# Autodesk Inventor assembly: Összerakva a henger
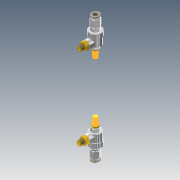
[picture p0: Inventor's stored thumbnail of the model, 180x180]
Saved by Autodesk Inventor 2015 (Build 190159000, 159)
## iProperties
Created: 2012-12
Part Number: Összerakva a henger
Document SubType Name: Assembly
Designer: Marci
Author: Marci
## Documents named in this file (5)
- C:\Users\Andrew Almeida\Documents\Projeto WS2015\WS2015 CAD Data ANLAS\01\Pneumatic System\Engine\Pneumatikus hajtás\Összerakva a henger.iam
- C:\Users\Andrew Almeida\Documents\Projeto WS2015\WS2015 CAD Data ANLAS\01\Pneumatic System\Engine\Pneumatikus hajtás\Hollanderes közcsavar.ipt
- C:\Users\Andrew Almeida\Documents\Projeto WS2015\WS2015 CAD Data ANLAS\01\Pneumatic System\Engine\Pneumatikus hajtás\Gyorsleeresztő szelep.ipt
- C:\Users\Andrew Almeida\Documents\Projeto WS2015\WS2015 CAD Data ANLAS\01\Pneumatic System\Engine\Pneumatikus hajtás\Hangtompító.ipt
- C:\Users\Andrew Almeida\Documents\Projeto WS2015\WS2015 CAD Data ANLAS\01\Pneumatic System\Engine\Pneumatikus hajtás\1.4 12 gyorscsat.ipt
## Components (8 placed, 4 different names)
1. Hollanderes közcsavar:1 — Mate:13, Mate:14
2. Hollanderes közcsavar:2 — Mate:11, Mate:12
3. Gyorsleeresztő szelep:1 — Mate:11, Mate:12, Flush:1, Mate:16, Mate:17, Mate:20, Mate:21
4. Gyorsleeresztő szelep:2 — Mate:13, Mate:14, Flush:2, Mate:18, Mate:19, Mate:22, Mate:23
5. Hangtompító:1 — Mate:16, Mate:17
6. Hangtompító:2 — Mate:18, Mate:19
7. 1.4 12 gyorscsat:1 — Mate:20, Mate:21
8. 1.4 12 gyorscsat:2 — Mate:22, Mate:23
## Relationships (14: Mate 12, Flush 2)
- Mate:11: Hollanderes közcsavar:2 ↔ Gyorsleeresztő szelep:1
- Mate:12: Hollanderes közcsavar:2 ↔ Gyorsleeresztő szelep:1
- Mate:13: Hollanderes közcsavar:1 ↔ Gyorsleeresztő szelep:2
- Mate:14: Hollanderes közcsavar:1 ↔ Gyorsleeresztő szelep:2
- Flush:1: Gyorsleeresztő szelep:1
- Flush:2: Gyorsleeresztő szelep:2
- Mate:16: Gyorsleeresztő szelep:1 ↔ Hangtompító:1
- Mate:17: Gyorsleeresztő szelep:1 ↔ Hangtompító:1
- Mate:18: Gyorsleeresztő szelep:2 ↔ Hangtompító:2
- Mate:19: Gyorsleeresztő szelep:2 ↔ Hangtompító:2
- Mate:20: Gyorsleeresztő szelep:1 ↔ 1.4 12 gyorscsat:1
- Mate:21: Gyorsleeresztő szelep:1 ↔ 1.4 12 gyorscsat:1
- Mate:22: Gyorsleeresztő szelep:2 ↔ 1.4 12 gyorscsat:2
- Mate:23: Gyorsleeresztő szelep:2 ↔ 1.4 12 gyorscsat:2
